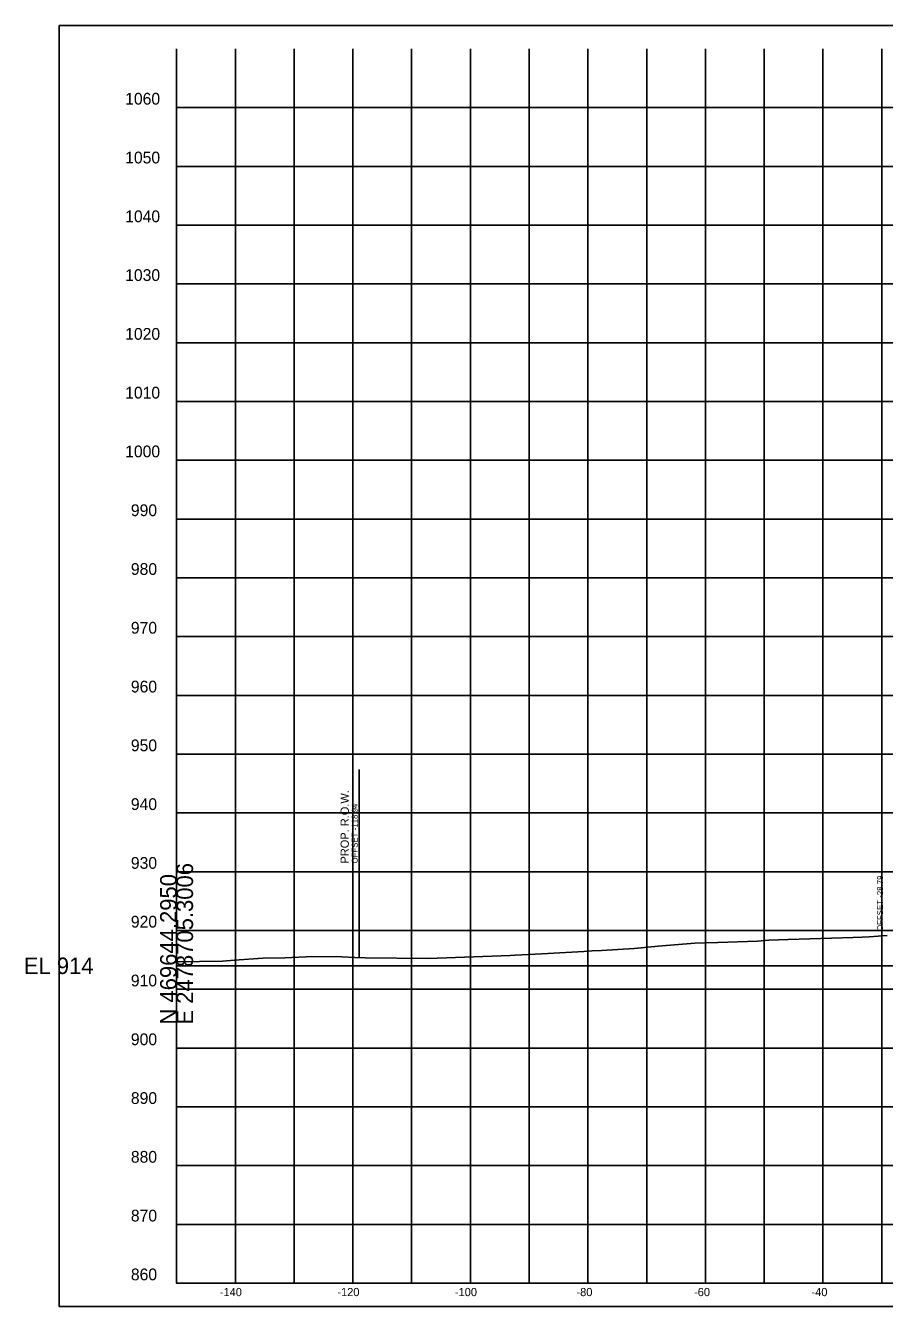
# Model space of a CAD drawing. Extents: x -26 to 2478923, y -10 to 469990.
# Drawn here: x -25.7 to 120.5, y 5442.1 to 5659.9 of the extents above; entities that cross this region are included whole.
import ezdxf

# ---------------------------------------------------------------- set-up
doc = ezdxf.new("R2010")
doc.units = 0
for name, color, linetype in [('DESIGN - ROW - Right-of-Way and Easement Labels', 7, 'Continuous'), ('DESIGN - ROW - Right-of-Way Linework', 7, 'Continuous'), ('DESIGN - SHEET - Corner Text', 7, 'Continuous'), ('DESIGN - SHEET - Light Grid', 7, 'Continuous'), ('DESIGN - SHEET - Linework', 7, 'Continuous'), ('DESIGN - SHEET - Plot Shape', 7, 'Continuous'), ('DESIGN - TYPICAL - Slope Tie Text', 7, 'Continuous'), ('SURVEY - GROUND - Top of Ground', 7, 'Continuous')]:
    doc.layers.add(name, color=color, linetype=linetype)

msp = doc.modelspace()

# ---------------------------------------------------------------- linework, layer by layer
at = {"layer": 'DESIGN - ROW - Right-of-Way Linework'}
msp.add_line((31.06, 5501.4), (31.06, 5533.4), dxfattribs=at)
at = {"layer": 'DESIGN - SHEET - Light Grid'}
msp.add_line((0, 5500), (150, 5500), dxfattribs=at)
at = {"layer": 'DESIGN - SHEET - Linework'}
for p, q in [((10, 5446), (10, 5656)), ((10, 5446), (10, 5656)), ((10, 5446), (10, 5656)), ((10, 5446), (10, 5656)), ((20, 5446), (20, 5656)), ((20, 5446), (20, 5656)), ((20, 5446), (20, 5656)), ((20, 5446), (20, 5656)), ((30, 5446), (30, 5656)), ((30, 5446), (30, 5656)), ((30, 5446), (30, 5656)), ((30, 5446), (30, 5656)), ((40, 5446), (40, 5656)), ((40, 5446), (40, 5656)), ((40, 5446), (40, 5656)), ((40, 5446), (40, 5656)), ((50, 5446), (50, 5656)), ((50, 5446), (50, 5656)), ((50, 5446), (50, 5656)), ((50, 5446), (50, 5656)), ((60, 5446), (60, 5656)), ((60, 5446), (60, 5656)), ((60, 5446), (60, 5656)), ((60, 5446), (60, 5656)), ((70, 5446), (70, 5656)), ((70, 5446), (70, 5656)), ((70, 5446), (70, 5656)), ((70, 5446), (70, 5656)), ((80, 5446), (80, 5656)), ((80, 5446), (80, 5656)), ((80, 5446), (80, 5656)), ((80, 5446), (80, 5656)), ((90, 5446), (90, 5656)), ((90, 5446), (90, 5656)), ((90, 5446), (90, 5656)), ((90, 5446), (90, 5656)), ((100, 5446), (100, 5656)), ((100, 5446), (100, 5656)), ((100, 5446), (100, 5656)), ((100, 5446), (100, 5656)), ((110, 5446), (110, 5656)), ((110, 5446), (110, 5656)), ((110, 5446), (110, 5656)), ((110, 5446), (110, 5656)), ((120, 5446), (120, 5656)), ((120, 5446), (120, 5656)), ((120, 5446), (120, 5656)), ((120, 5446), (120, 5656)), ((0, 5646), (300, 5646)), ((0, 5646), (300, 5646)), ((0, 5646), (300, 5646)), ((0, 5646), (300, 5646)), ((0, 5636), (300, 5636)), ((0, 5636), (300, 5636)), ((0, 5636), (300, 5636)), ((0, 5636), (300, 5636)), ((0, 5626), (300, 5626)), ((0, 5626), (300, 5626)), ((0, 5626), (300, 5626)), ((0, 5626), (300, 5626)), ((0, 5616), (300, 5616)), ((0, 5616), (300, 5616)), ((0, 5616), (300, 5616)), ((0, 5616), (300, 5616)), ((0, 5606), (300, 5606)), ((0, 5606), (300, 5606)), ((0, 5606), (300, 5606)), ((0, 5606), (300, 5606)), ((0, 5596), (300, 5596)), ((0, 5596), (300, 5596)), ((0, 5596), (300, 5596)), ((0, 5596), (300, 5596)), ((0, 5586), (300, 5586)), ((0, 5586), (300, 5586)), ((0, 5586), (300, 5586)), ((0, 5586), (300, 5586)), ((0, 5576), (300, 5576)), ((0, 5576), (300, 5576)), ((0, 5576), (300, 5576)), ((0, 5576), (300, 5576)), ((0, 5566), (300, 5566)), ((0, 5566), (300, 5566)), ((0, 5566), (300, 5566)), ((0, 5566), (300, 5566)), ((0, 5556), (300, 5556)), ((0, 5556), (300, 5556)), ((0, 5556), (300, 5556)), ((0, 5556), (300, 5556)), ((0, 5546), (300, 5546)), ((0, 5546), (300, 5546)), ((0, 5546), (300, 5546)), ((0, 5546), (300, 5546)), ((0, 5536), (300, 5536)), ((0, 5536), (300, 5536)), ((0, 5536), (300, 5536)), ((0, 5536), (300, 5536)), ((0, 5526), (300, 5526)), ((0, 5526), (300, 5526)), ((0, 5526), (300, 5526)), ((0, 5526), (300, 5526)), ((0, 5516), (300, 5516)), ((0, 5516), (300, 5516)), ((0, 5516), (300, 5516)), ((0, 5516), (300, 5516)), ((0, 5506), (300, 5506)), ((0, 5506), (300, 5506)), ((0, 5506), (300, 5506)), ((0, 5506), (300, 5506)), ((0, 5496), (300, 5496)), ((0, 5496), (300, 5496)), ((0, 5496), (300, 5496)), ((0, 5496), (300, 5496)), ((0, 5486), (300, 5486)), ((0, 5486), (300, 5486)), ((0, 5486), (300, 5486)), ((0, 5486), (300, 5486)), ((0, 5476), (300, 5476)), ((0, 5476), (300, 5476)), ((0, 5476), (300, 5476)), ((0, 5476), (300, 5476)), ((0, 5466), (300, 5466)), ((0, 5466), (300, 5466)), ((0, 5466), (300, 5466)), ((0, 5466), (300, 5466)), ((0, 5456), (300, 5456)), ((0, 5456), (300, 5456)), ((0, 5456), (300, 5456)), ((0, 5456), (300, 5456))]:
    msp.add_line(p, q, dxfattribs=at)
msp.add_lwpolyline([(0, 5656), (0, 5446), (300, 5446), (300, 5656)], dxfattribs=at)
msp.add_lwpolyline([(0, 5656), (0, 5446), (300, 5446), (300, 5656)], dxfattribs=at)
msp.add_lwpolyline([(0, 5656), (0, 5446), (300, 5446), (300, 5656)], dxfattribs=at)
msp.add_lwpolyline([(0, 5656), (0, 5446), (300, 5446), (300, 5656)], dxfattribs=at)
at = {"layer": 'DESIGN - SHEET - Plot Shape'}
msp.add_lwpolyline([(-20, 5659.94), (320, 5659.94), (320, 5442.06), (-20, 5442.06)], close=True, dxfattribs=at)
msp.add_lwpolyline([(-20, 5659.94), (320, 5659.94), (320, 5442.06), (-20, 5442.06)], close=True, dxfattribs=at)
msp.add_lwpolyline([(-20, 5659.94), (320, 5659.94), (320, 5442.06), (-20, 5442.06)], close=True, dxfattribs=at)
msp.add_lwpolyline([(-20, 5659.94), (320, 5659.94), (320, 5442.06), (-20, 5442.06)], close=True, dxfattribs=at)
at = {"layer": 'SURVEY - GROUND - Top of Ground'}
msp.add_lwpolyline([(0, 5500.68), (7.82, 5500.78), (8.48, 5500.83), (9.88, 5500.95), (14.66, 5501.27), (18.43, 5501.38), (23.22, 5501.56), (28.11, 5501.52), (30.36, 5501.43), (32.11, 5501.35), (42.84, 5501.26), (56.74, 5501.76), (57.6, 5501.78), (62.18, 5502.02), (69.32, 5502.43), (70.72, 5502.52), (72.32, 5502.62), (77.89, 5502.94), (81.95, 5503.35), (88.21, 5503.83), (92.11, 5503.96), (98.83, 5504.21), (100.79, 5504.35), (104.09, 5504.5), (115.11, 5504.81), (116.69, 5504.88), (117.84, 5504.93), (120.9, 5505.14)], dxfattribs=at)

# ---------------------------------------------------------------- texts
at = {"layer": 'DESIGN - ROW - Right-of-Way and Easement Labels'}
for s, height, p in [('PROP. R.O.W.', 1.4, (29.31, 5517.4)), ('OFFSET -118.94', 1, (30.81, 5517.4))]:
    msp.add_text(s, height=height, rotation=90, dxfattribs=at).set_placement(p)
at = {"layer": 'DESIGN - SHEET - Corner Text'}
for s, height, p in [('1060', 2, (-8.75, 5646.5)), ('1060', 2, (-8.75, 5646.5)), ('1060', 2, (-8.75, 5646.5)), ('1060', 2, (-8.75, 5646.5)), ('1050', 2, (-8.75, 5636.5)), ('1050', 2, (-8.75, 5636.5)), ('1050', 2, (-8.75, 5636.5)), ('1050', 2, (-8.75, 5636.5)), ('1040', 2, (-8.75, 5626.5)), ('1040', 2, (-8.75, 5626.5)), ('1040', 2, (-8.75, 5626.5)), ('1040', 2, (-8.75, 5626.5)), ('1030', 2, (-8.75, 5616.5)), ('1030', 2, (-8.75, 5616.5)), ('1030', 2, (-8.75, 5616.5)), ('1030', 2, (-8.75, 5616.5)), ('1020', 2, (-8.75, 5606.5)), ('1020', 2, (-8.75, 5606.5)), ('1020', 2, (-8.75, 5606.5)), ('1020', 2, (-8.75, 5606.5)), ('1010', 2, (-8.75, 5596.5)), ('1010', 2, (-8.75, 5596.5)), ('1010', 2, (-8.75, 5596.5)), ('1010', 2, (-8.75, 5596.5)), ('1000', 2, (-8.75, 5586.5)), ('1000', 2, (-8.75, 5586.5)), ('1000', 2, (-8.75, 5586.5)), ('1000', 2, (-8.75, 5586.5)), ('990', 2, (-7.78, 5576.5)), ('990', 2, (-7.78, 5576.5)), ('990', 2, (-7.78, 5576.5)), ('990', 2, (-7.78, 5576.5)), ('980', 2, (-7.78, 5566.5)), ('980', 2, (-7.78, 5566.5)), ('980', 2, (-7.78, 5566.5)), ('980', 2, (-7.78, 5566.5)), ('970', 2, (-7.78, 5556.5)), ('970', 2, (-7.78, 5556.5)), ('970', 2, (-7.78, 5556.5)), ('970', 2, (-7.78, 5556.5)), ('960', 2, (-7.78, 5546.5)), ('960', 2, (-7.78, 5546.5)), ('960', 2, (-7.78, 5546.5)), ('960', 2, (-7.78, 5546.5)), ('950', 2, (-7.78, 5536.5)), ('950', 2, (-7.78, 5536.5)), ('950', 2, (-7.78, 5536.5)), ('950', 2, (-7.78, 5536.5)), ('940', 2, (-7.78, 5526.5)), ('940', 2, (-7.78, 5526.5)), ('940', 2, (-7.78, 5526.5)), ('940', 2, (-7.78, 5526.5)), ('930', 2, (-7.78, 5516.5)), ('930', 2, (-7.78, 5516.5)), ('930', 2, (-7.78, 5516.5)), ('930', 2, (-7.78, 5516.5)), ('920', 2, (-7.78, 5506.5)), ('920', 2, (-7.78, 5506.5)), ('920', 2, (-7.78, 5506.5)), ('920', 2, (-7.78, 5506.5)), ('910', 2, (-7.78, 5496.5)), ('910', 2, (-7.78, 5496.5)), ('910', 2, (-7.78, 5496.5)), ('910', 2, (-7.78, 5496.5)), ('900', 2, (-7.78, 5486.5)), ('900', 2, (-7.78, 5486.5)), ('900', 2, (-7.78, 5486.5)), ('900', 2, (-7.78, 5486.5)), ('890', 2, (-7.78, 5476.5)), ('890', 2, (-7.78, 5476.5)), ('890', 2, (-7.78, 5476.5)), ('890', 2, (-7.78, 5476.5)), ('880', 2, (-7.78, 5466.5)), ('880', 2, (-7.78, 5466.5)), ('880', 2, (-7.78, 5466.5)), ('880', 2, (-7.78, 5466.5)), ('870', 2, (-7.78, 5456.5)), ('870', 2, (-7.78, 5456.5)), ('870', 2, (-7.78, 5456.5)), ('870', 2, (-7.78, 5456.5)), ('860', 2, (-7.78, 5446.5)), ('860', 2, (-7.78, 5446.5)), ('860', 2, (-7.78, 5446.5)), ('860', 2, (-7.78, 5446.5)), ('-140', 1.4, (7.37, 5443.8)), ('-140', 1.4, (7.37, 5443.8)), ('-140', 1.4, (7.37, 5443.8)), ('-140', 1.4, (7.37, 5443.8)), ('-120', 1.4, (27.37, 5443.8)), ('-120', 1.4, (27.37, 5443.8)), ('-120', 1.4, (27.37, 5443.8)), ('-120', 1.4, (27.37, 5443.8)), ('-100', 1.4, (47.37, 5443.8)), ('-100', 1.4, (47.37, 5443.8)), ('-100', 1.4, (47.37, 5443.8)), ('-100', 1.4, (47.37, 5443.8)), ('-80', 1.4, (68.06, 5443.8)), ('-80', 1.4, (68.06, 5443.8)), ('-80', 1.4, (68.06, 5443.8)), ('-80', 1.4, (68.06, 5443.8)), ('-60', 1.4, (88.06, 5443.8)), ('-60', 1.4, (88.06, 5443.8)), ('-60', 1.4, (88.06, 5443.8)), ('-60', 1.4, (88.06, 5443.8)), ('-40', 1.4, (108.06, 5443.8)), ('-40', 1.4, (108.06, 5443.8)), ('-40', 1.4, (108.06, 5443.8)), ('-40', 1.4, (108.06, 5443.8))]:
    msp.add_text(s, height=height, dxfattribs=at).set_placement(p)
at = {"layer": 'DESIGN - SHEET - Light Grid'}
for s, p in [('E 2478705.3006', (2.8, 5490)), ('N 469644.2950', (0, 5490))]:
    msp.add_text(s, height=2.8, rotation=90, dxfattribs=at).set_placement(p)
msp.add_text('EL 914', height=2.8, dxfattribs=at).set_placement((-26, 5498.6))
at = {"layer": 'DESIGN - TYPICAL - Slope Tie Text'}
msp.add_text('OFFSET -28.79', height=1, rotation=90, dxfattribs=at).set_placement((120.21, 5505.92))

doc.saveas('drawing.dxf')
